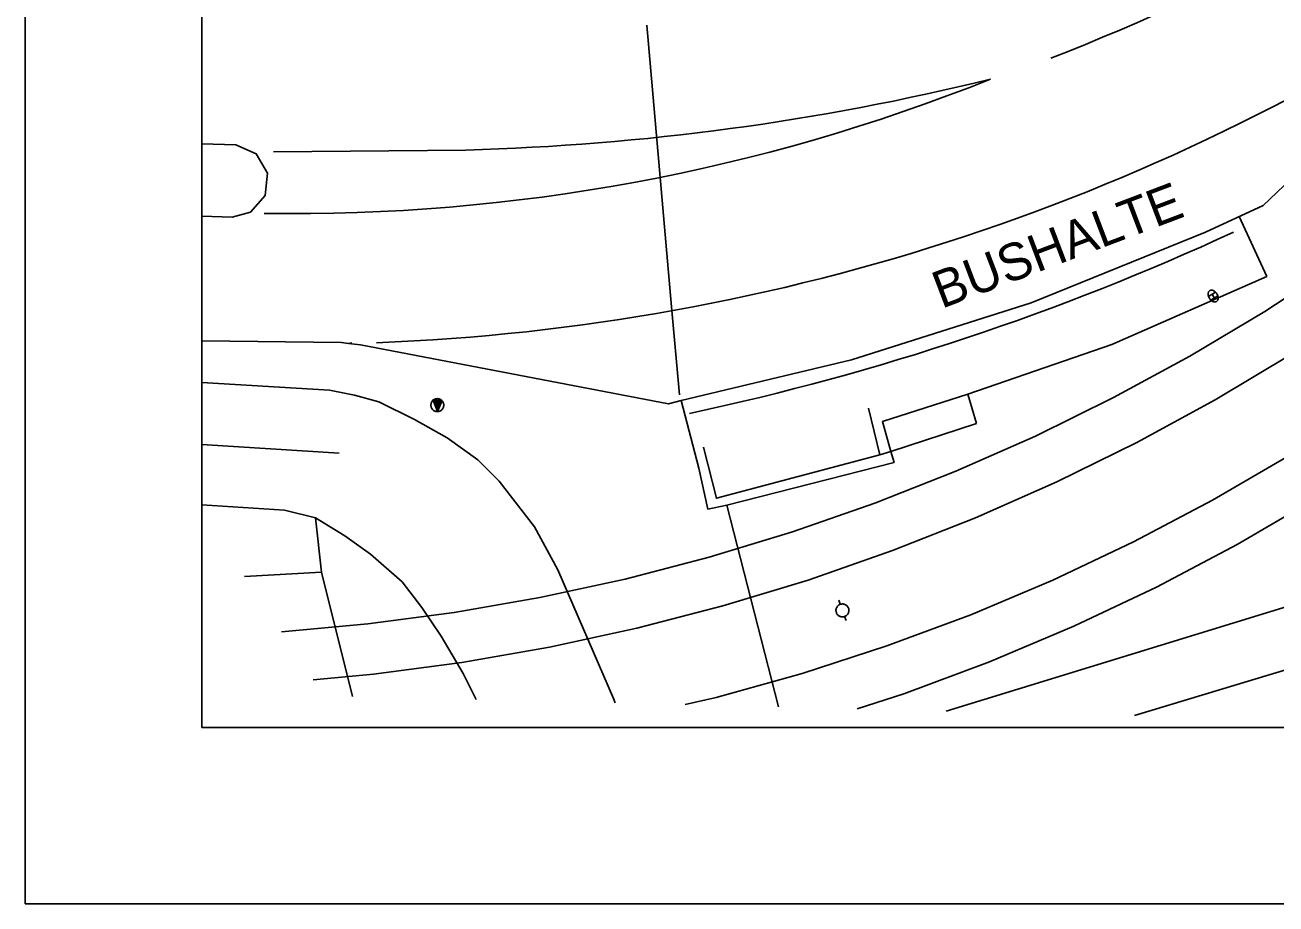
# Model space of a CAD drawing. Extents: x 81065 to 81486, y 452384 to 452681.
# Drawn here: x 81065.21 to 81100.63, y 452383.53 to 452408.42 of the extents above; entities that cross this region are included whole.
import ezdxf

# ---------------------------------------------------------------- set-up
doc = ezdxf.new("R2010")
doc.units = 0
for name, color, linetype in [('B-BH-AL-TOPOGRAFIE_STRAATNAAM-S', 7, 'Continuous'), ('B-BH-GR-GROENVOORZIENING-GV', 7, 'Continuous'), ('B-BH-IE-MEUBILAIR-WEGMEUBILAIR-VERKEERSBORD-S', 7, 'Continuous'), ('B-BH-IE-MEUBILAIR_WEGMEUBILAIR_ABRI-S', 7, 'Continuous'), ('B-BH-IE-MEUBILAIR_WEGMEUBILAIR_TRAMMAST-S', 7, 'Continuous'), ('B-BH-OG-TERREIN_ERF-GV', 7, 'Continuous'), ('B-BH-RI-HWA_GOOT_LIJNGOOT-G', 7, 'Continuous'), ('B-BH-VH-KANTOPSLUITING-GV', 7, 'Continuous'), ('B-SB-OG-WEG_SPOOR_TRAM-G', 7, 'Continuous'), ('B-WE-VW-MARKERING-G', 7, 'Continuous'), ('B-WE-VW-MARKERING_LANGS_STREEP_13_010-G', 7, 'Continuous'), ('B-WE-VW-MARKERING_LANGS_STREEP_30270_010-G', 7, 'Continuous'), ('B-WE-VW-MARKERING_LANGS_STREEP_DOORGETROKKEN_010-G', 7, 'Continuous'), ('X-XX-AL-TEKENBLAD_KADER-G', 7, 'Continuous'), ('X-XX-AL-TEKENBLAD_KADER_AFSNIJMARKERING-G', 7, 'Continuous'), ('X-XX-AL-TEKENBLAD_VIEWPORT-G', 7, 'Continuous')]:
    doc.layers.add(name, color=color, linetype=linetype)

msp = doc.modelspace()

# ---------------------------------------------------------------- linework, layer by layer
at = {"layer": 'B-BH-GR-GROENVOORZIENING-GV'}
msp.add_lwpolyline([(81071.428, 452392.806), (81073.612, 452392.931)], dxfattribs=at)
at = {"layer": 'B-BH-IE-MEUBILAIR-WEGMEUBILAIR-VERKEERSBORD-S'}
for p, q in [((81076.755, 452397.786), (81077.02, 452397.786)), ((81076.888, 452397.477), (81076.777, 452397.768)), ((81076.777, 452397.768), (81076.993, 452397.768)), ((81076.804, 452397.75), (81076.965, 452397.75)), ((81076.889, 452397.526), (81076.804, 452397.75)), ((81076.89, 452397.575), (81076.83, 452397.731)), ((81076.83, 452397.731), (81076.937, 452397.731)), ((81076.891, 452397.624), (81076.857, 452397.713)), ((81076.857, 452397.713), (81076.909, 452397.713)), ((81076.892, 452397.672), (81076.883, 452397.695)), ((81077.02, 452397.786), (81076.888, 452397.477)), ((81076.993, 452397.768), (81076.889, 452397.526)), ((81076.965, 452397.75), (81076.89, 452397.575)), ((81076.937, 452397.731), (81076.891, 452397.624)), ((81076.909, 452397.713), (81076.892, 452397.672))]:
    msp.add_line(p, q, dxfattribs=at)
msp.add_lwpolyline([(81076.705, 452397.66), (81076.706, 452397.641), (81076.709, 452397.622), (81076.714, 452397.603), (81076.721, 452397.585), (81076.729, 452397.568), (81076.74, 452397.552), (81076.752, 452397.537), (81076.765, 452397.524), (81076.78, 452397.512), (81076.796, 452397.501), (81076.813, 452397.493), (81076.831, 452397.486), (81076.85, 452397.481), (81076.869, 452397.478), (81076.888, 452397.477), (81076.907, 452397.478), (81076.926, 452397.481), (81076.945, 452397.486), (81076.962, 452397.493), (81076.979, 452397.501), (81076.996, 452397.512), (81077.01, 452397.524), (81077.024, 452397.537), (81077.036, 452397.552), (81077.046, 452397.568), (81077.055, 452397.585), (81077.062, 452397.603), (81077.067, 452397.622), (81077.07, 452397.641), (81077.071, 452397.66), (81077.07, 452397.679), (81077.067, 452397.698), (81077.062, 452397.717), (81077.055, 452397.734), (81077.046, 452397.751), (81077.036, 452397.768), (81077.024, 452397.782), (81077.01, 452397.796), (81076.996, 452397.808), (81076.979, 452397.818), (81076.962, 452397.827), (81076.945, 452397.834), (81076.926, 452397.839), (81076.907, 452397.842), (81076.888, 452397.843), (81076.869, 452397.842), (81076.85, 452397.839), (81076.831, 452397.834), (81076.813, 452397.827), (81076.796, 452397.818), (81076.78, 452397.808), (81076.765, 452397.796), (81076.752, 452397.782), (81076.74, 452397.768), (81076.729, 452397.751), (81076.721, 452397.734), (81076.714, 452397.717), (81076.709, 452397.698), (81076.706, 452397.679), (81076.705, 452397.66)], dxfattribs=at)
at = {"layer": 'B-BH-IE-MEUBILAIR_WEGMEUBILAIR_ABRI-S'}
msp.add_lwpolyline([(81089.099, 452397.57), (81089.418, 452396.248), (81084.788, 452395.022), (81084.428, 452396.472)], dxfattribs=at)
at = {"layer": 'B-BH-IE-MEUBILAIR_WEGMEUBILAIR_TRAMMAST-S'}
for p, q in [((81098.724, 452400.74), (81098.92, 452400.861)), ((81098.788, 452400.636), (81098.984, 452400.758)), ((81098.886, 452400.697), (81098.822, 452400.801)), ((81088.295, 452392.018), (81088.253, 452392.133)), ((81088.461, 452391.559), (81088.419, 452391.674))]:
    msp.add_line(p, q, dxfattribs=at)
for points in [[(81098.758, 452400.904), (81098.747, 452400.897), (81098.738, 452400.888), (81098.73, 452400.877), (81098.724, 452400.865), (81098.719, 452400.851), (81098.715, 452400.837), (81098.713, 452400.821), (81098.712, 452400.805), (81098.713, 452400.788), (81098.716, 452400.771), (81098.72, 452400.753), (81098.725, 452400.736), (81098.732, 452400.718), (81098.741, 452400.701), (81098.75, 452400.685), (81098.761, 452400.669), (81098.772, 452400.654), (81098.785, 452400.639), (81098.798, 452400.627), (81098.812, 452400.615), (81098.827, 452400.605), (81098.841, 452400.597), (81098.856, 452400.59), (81098.871, 452400.585), (81098.885, 452400.582), (81098.9, 452400.58), (81098.913, 452400.581), (81098.927, 452400.583), (81098.939, 452400.587), (81098.95, 452400.593), (81098.961, 452400.601), (81098.97, 452400.61), (81098.978, 452400.62), (81098.984, 452400.633), (81098.989, 452400.646), (81098.993, 452400.66), (81098.995, 452400.676), (81098.995, 452400.692), (81098.995, 452400.709), (81098.992, 452400.727), (81098.988, 452400.744), (81098.982, 452400.762), (81098.975, 452400.779), (81098.967, 452400.796), (81098.958, 452400.813), (81098.947, 452400.829), (81098.935, 452400.844), (81098.923, 452400.858), (81098.91, 452400.871), (81098.896, 452400.882), (81098.881, 452400.892), (81098.867, 452400.901), (81098.852, 452400.907), (81098.837, 452400.912), (81098.822, 452400.916), (81098.808, 452400.917), (81098.794, 452400.917), (81098.781, 452400.914), (81098.769, 452400.91), (81098.758, 452400.904)], [(81088.295, 452392.018), (81088.277, 452392.01), (81088.26, 452392.001), (81088.245, 452391.99), (81088.23, 452391.978), (81088.217, 452391.964), (81088.206, 452391.949), (81088.196, 452391.932), (81088.187, 452391.915), (81088.181, 452391.897), (81088.177, 452391.878), (81088.174, 452391.859), (81088.174, 452391.84), (81088.176, 452391.821), (81088.179, 452391.802), (81088.185, 452391.784), (81088.192, 452391.766), (81088.201, 452391.749), (81088.212, 452391.733), (81088.225, 452391.719), (81088.239, 452391.706), (81088.254, 452391.694), (81088.271, 452391.684), (81088.288, 452391.676), (81088.306, 452391.67), (81088.325, 452391.666), (81088.344, 452391.663), (81088.363, 452391.663), (81088.382, 452391.664), (81088.401, 452391.668), (81088.419, 452391.674), (81088.437, 452391.681), (81088.454, 452391.69), (81088.469, 452391.701), (81088.484, 452391.714), (81088.497, 452391.728), (81088.509, 452391.743), (81088.518, 452391.759), (81088.527, 452391.777), (81088.533, 452391.795), (81088.537, 452391.814), (81088.54, 452391.833), (81088.54, 452391.852), (81088.538, 452391.871), (81088.535, 452391.89), (81088.529, 452391.908), (81088.522, 452391.926), (81088.513, 452391.942), (81088.502, 452391.958), (81088.489, 452391.973), (81088.475, 452391.986), (81088.46, 452391.997), (81088.443, 452392.007), (81088.426, 452392.015), (81088.408, 452392.022), (81088.389, 452392.026), (81088.37, 452392.028), (81088.351, 452392.029), (81088.332, 452392.027), (81088.313, 452392.024), (81088.295, 452392.018)]]:
    msp.add_lwpolyline(points, dxfattribs=at)
at = {"layer": 'B-BH-OG-TERREIN_ERF-GV'}
for p, q in [((81091.905, 452397.968), (81092.15, 452397.14)), ((81092.15, 452397.14), (81089.728, 452396.349)), ((81089.728, 452396.349), (81089.418, 452396.248))]:
    msp.add_line(p, q, dxfattribs=at)
at = {"layer": 'B-BH-RI-HWA_GOOT_LIJNGOOT-G'}
msp.add_lwpolyline([(81083.74, 452397.949), (81083.521, 452400.445), (81082.824, 452408.421)], dxfattribs=at)
at = {"layer": 'B-BH-VH-KANTOPSLUITING-GV'}
for p, q in [((81100.269, 452403.315), (81107.845, 452410.527)), ((81100.37, 452401.299), (81099.593, 452403.001)), ((81074.468, 452399.421), (81074.368, 452399.409)), ((81091.294, 452388.997), (81113.998, 452395.951)), ((81085.081, 452394.825), (81086.545, 452389.114)), ((81073.612, 452392.931), (81073.443, 452394.469)), ((81112.147, 452393.585), (81096.63, 452388.866)), ((81074.482, 452389.41), (81073.612, 452392.931))]:
    msp.add_line(p, q, dxfattribs=at)
for points in [[(81070.22, 452403.01), (81071.076, 452402.979), (81071.597, 452403.121), (81072.018, 452403.595), (81072.081, 452404.225), (81071.762, 452404.773), (81071.183, 452405.03), (81070.22, 452405.061)], [(81100.269, 452403.315), (81098.639, 452402.558), (81093.697, 452400.56), (81088.618, 452398.938), (81083.79, 452397.786)], [(81091.905, 452397.968), (81095.987, 452399.38), (81100.37, 452401.299)], [(81074.368, 452399.409), (81074.176, 452399.434), (81070.22, 452399.477)], [(81074.368, 452399.409), (81074.712, 452399.363), (81083.432, 452397.701), (81083.79, 452397.786)], [(81070.22, 452398.303), (81073.839, 452398.083), (81074.544, 452397.944)], [(81074.544, 452397.944), (81075.23, 452397.755), (81076.242, 452397.257), (81077.162, 452396.737), (81078.037, 452396.111), (81078.641, 452395.507), (81079.64, 452394.217), (81080.298, 452392.998), (81081.875, 452389.349), (81081.919, 452389.227)], [(81089.728, 452396.349), (81089.487, 452397.198), (81091.905, 452397.968)], [(81083.79, 452397.786), (81084.294, 452395.874), (81084.543, 452394.716), (81085.081, 452394.825)], [(81085.081, 452394.825), (81089.818, 452396.036), (81089.728, 452396.349)], [(81073.443, 452394.469), (81072.559, 452394.689), (81070.22, 452394.833)], [(81077.986, 452389.324), (81077.622, 452390.063), (81076.996, 452391.121), (81076.446, 452391.931), (81075.895, 452392.654), (81074.991, 452393.437), (81074.265, 452393.96), (81073.443, 452394.469)]]:
    msp.add_lwpolyline(points, dxfattribs=at)
at = {"layer": 'B-SB-OG-WEG_SPOOR_TRAM-G'}
for points in [[(81091.566, 452395.787), (81093.82, 452396.784), (81096.032, 452397.873), (81098.197, 452399.05), (81100.313, 452400.314), (81102.376, 452401.662), (81104.383, 452403.094), (81108.058, 452406.052), (81128.086, 452424.061), (81138.732, 452433.407), (81144.254, 452437.992)], [(81073.376, 452389.882), (81075.079, 452390.039), (81077.581, 452390.371), (81080.067, 452390.805), (81082.533, 452391.34), (81084.975, 452391.974), (81087.39, 452392.707), (81089.773, 452393.538), (81092.121, 452394.464), (81094.428, 452395.485), (81096.693, 452396.599), (81098.91, 452397.805), (81101.076, 452399.099), (81103.188, 452400.48), (81105.243, 452401.945), (81109.072, 452405.032), (81127.365, 452421.484), (81136.586, 452429.669)], [(81132.047, 452422.791), (81108.447, 452401.618), (81105.218, 452399.064), (81103.151, 452397.608), (81101.023, 452396.242), (81098.839, 452394.968), (81096.602, 452393.789), (81094.317, 452392.706), (81091.988, 452391.723), (81089.619, 452390.839), (81087.214, 452390.059), (81084.778, 452389.381), (81083.906, 452389.179)], [(81111.932, 452402.757), (81110.04, 452401.091), (81106.073, 452397.911), (81103.955, 452396.419), (81101.775, 452395.02), (81099.537, 452393.715), (81097.246, 452392.507), (81094.905, 452391.398), (81092.518, 452390.39), (81090.091, 452389.485), (81088.779, 452389.059)], [(81072.472, 452391.239), (81074.921, 452391.464), (81077.365, 452391.789), (81079.793, 452392.213), (81082.202, 452392.735), (81084.587, 452393.355), (81086.946, 452394.071), (81089.273, 452394.882), (81091.566, 452395.787)]]:
    msp.add_lwpolyline(points, dxfattribs=at)
at = {"layer": 'B-WE-VW-MARKERING-G'}
msp.add_arc((81068.749, 452468.943), 73.131, 282.06256, 294.80265, dxfattribs=at)
at = {"layer": 'B-WE-VW-MARKERING_LANGS_STREEP_13_010-G'}
msp.add_arc((81069.938, 452469.634), 66.74, 291.37072, 305.82624, dxfattribs=at)
at = {"layer": 'B-WE-VW-MARKERING_LANGS_STREEP_30270_010-G'}
msp.add_line((81070.22, 452396.542), (81074.106, 452396.302), dxfattribs=at)
at = {"layer": 'B-WE-VW-MARKERING_LANGS_STREEP_DOORGETROKKEN_010-G'}
msp.add_line((81072.249, 452404.833), (81077.695, 452404.885), dxfattribs=at)
for centre, radius, start, end in [((81072.901, 452459.564), 60.178, 272.15386, 304.47568), ((81072.817, 452456.115), 53.031, 269.0978, 291.8416), ((81075.79, 452474.995), 70.136, 271.55608, 283.82237)]:
    msp.add_arc(centre, radius, start, end, dxfattribs=at)
at = {"layer": 'X-XX-AL-TEKENBLAD_KADER-G'}
msp.add_lwpolyline([(81480.708, 452388.532), (81070.22, 452388.532), (81070.22, 452675.532), (81480.708, 452675.532)], close=True, dxfattribs=at)
at = {"layer": 'X-XX-AL-TEKENBLAD_KADER_AFSNIJMARKERING-G'}
msp.add_lwpolyline([(81485.714, 452680.532), (81065.214, 452680.532), (81065.214, 452383.532), (81485.714, 452383.532)], close=True, dxfattribs=at)
at = {"layer": 'X-XX-AL-TEKENBLAD_VIEWPORT-G'}
msp.add_lwpolyline([(81070.22, 452388.532), (81480.708, 452388.532), (81480.708, 452675.532), (81070.22, 452675.532)], close=True, dxfattribs=at)

# ---------------------------------------------------------------- texts
at = {"layer": 'B-BH-AL-TOPOGRAFIE_STRAATNAAM-S'}
msp.add_text('BUSHALTE', height=1.05, rotation=20.8051, dxfattribs=at).set_placement((81091.162, 452400.382))

doc.saveas('drawing.dxf')
